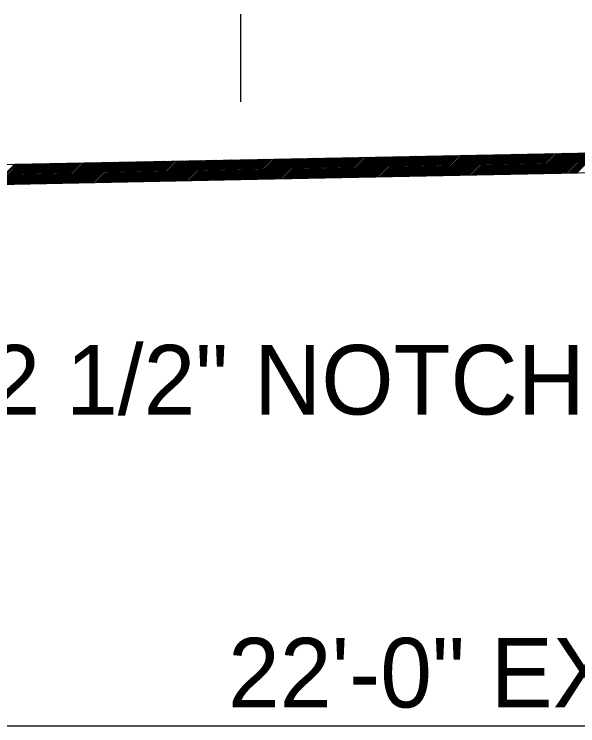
# Model space of a CAD drawing. Extents: x 2263886 to 2266026, y -3122850 to -3121850.
# Drawn here: x 2265591.65 to 2265596.51, y -3122413.5 to -3122407.37 of the extents above; entities that cross this region are included whole.
import ezdxf

# ---------------------------------------------------------------- set-up
doc = ezdxf.new("R2010")
doc.units = 0
doc.layers.add('R_Border Prem', color=7, linetype='Continuous')

msp = doc.modelspace()

# ---------------------------------------------------------------- linework, layer by layer
at = {"layer": 'R_Border Prem'}
for p, q in [((2265593.5991, -3122407.368), (2265593.5991, -3122408.123)), ((2265593.5991, -3122408.6231), (2265599.5991, -3122408.5031)), ((2265594.8123, -3122408.7688), (2265594.9858, -3122408.5953)), ((2265594.8267, -3122408.7685), (2265595.0002, -3122408.595)), ((2265594.8412, -3122408.7682), (2265595.0147, -3122408.5947)), ((2265594.8556, -3122408.768), (2265595.0291, -3122408.5945)), ((2265594.87, -3122408.7677), (2265595.0435, -3122408.5942)), ((2265594.8845, -3122408.7674), (2265595.058, -3122408.5939)), ((2265594.8989, -3122408.7671), (2265595.0724, -3122408.5936)), ((2265594.9133, -3122408.7668), (2265595.0868, -3122408.5933)), ((2265594.9278, -3122408.7665), (2265595.1013, -3122408.593)), ((2265594.9422, -3122408.7662), (2265595.1157, -3122408.5927)), ((2265594.9566, -3122408.7659), (2265595.1301, -3122408.5924)), ((2265594.971, -3122408.7656), (2265595.1446, -3122408.5921)), ((2265594.9855, -3122408.7654), (2265595.159, -3122408.5919)), ((2265594.9999, -3122408.7651), (2265595.1734, -3122408.5916)), ((2265595.0143, -3122408.7648), (2265595.1878, -3122408.5913)), ((2265595.0288, -3122408.7645), (2265595.2023, -3122408.591)), ((2265595.0432, -3122408.7642), (2265595.2167, -3122408.5907)), ((2265595.0576, -3122408.7639), (2265595.2311, -3122408.5904)), ((2265595.0721, -3122408.7636), (2265595.2456, -3122408.5901)), ((2265595.0865, -3122408.7633), (2265595.26, -3122408.5898)), ((2265595.1009, -3122408.7631), (2265595.2744, -3122408.5895)), ((2265595.1154, -3122408.7628), (2265595.2889, -3122408.5893)), ((2265595.1298, -3122408.7625), (2265595.3033, -3122408.589)), ((2265595.1442, -3122408.7622), (2265595.3177, -3122408.5887)), ((2265595.1586, -3122408.7619), (2265595.3322, -3122408.5884)), ((2265595.1731, -3122408.7616), (2265595.3466, -3122408.5881)), ((2265595.1875, -3122408.7613), (2265595.361, -3122408.5878)), ((2265595.2019, -3122408.761), (2265595.3754, -3122408.5875)), ((2265595.2164, -3122408.7607), (2265595.3899, -3122408.5872)), ((2265595.2308, -3122408.7605), (2265595.4043, -3122408.587)), ((2265595.2452, -3122408.7602), (2265595.4187, -3122408.5867)), ((2265595.2597, -3122408.7599), (2265595.4332, -3122408.5864)), ((2265595.2741, -3122408.7596), (2265595.4476, -3122408.5861)), ((2265595.2885, -3122408.7593), (2265595.462, -3122408.5858)), ((2265595.303, -3122408.759), (2265595.4765, -3122408.5855)), ((2265595.3174, -3122408.7587), (2265595.4909, -3122408.5852)), ((2265595.3318, -3122408.7584), (2265595.5053, -3122408.5849)), ((2265595.3462, -3122408.7581), (2265595.5197, -3122408.5846)), ((2265595.3607, -3122408.7579), (2265595.5342, -3122408.5844)), ((2265595.3751, -3122408.7576), (2265595.5486, -3122408.5841)), ((2265595.3895, -3122408.7573), (2265595.563, -3122408.5838)), ((2265595.404, -3122408.757), (2265595.5775, -3122408.5835)), ((2265595.4184, -3122408.7567), (2265595.5919, -3122408.5832)), ((2265595.4328, -3122408.7564), (2265595.6063, -3122408.5829)), ((2265595.4473, -3122408.7561), (2265595.6208, -3122408.5826)), ((2265595.4617, -3122408.7558), (2265595.6352, -3122408.5823)), ((2265595.4761, -3122408.7555), (2265595.6496, -3122408.582)), ((2265595.4906, -3122408.7553), (2265595.6641, -3122408.5818)), ((2265595.505, -3122408.755), (2265595.6785, -3122408.5815)), ((2265595.5194, -3122408.7547), (2265595.6929, -3122408.5812)), ((2265595.5338, -3122408.7544), (2265595.7073, -3122408.5809)), ((2265595.5483, -3122408.7541), (2265595.7218, -3122408.5806)), ((2265595.5627, -3122408.7538), (2265595.7362, -3122408.5803)), ((2265595.5771, -3122408.7535), (2265595.7506, -3122408.58)), ((2265595.5916, -3122408.7532), (2265595.7651, -3122408.5797)), ((2265595.606, -3122408.753), (2265595.7795, -3122408.5794)), ((2265595.6204, -3122408.7527), (2265595.7939, -3122408.5792)), ((2265595.6349, -3122408.7524), (2265595.8084, -3122408.5789)), ((2265595.6493, -3122408.7521), (2265595.8228, -3122408.5786)), ((2265595.6637, -3122408.7518), (2265595.8372, -3122408.5783)), ((2265595.6782, -3122408.7515), (2265595.8517, -3122408.578)), ((2265595.6926, -3122408.7512), (2265595.8661, -3122408.5777)), ((2265595.707, -3122408.7509), (2265595.8805, -3122408.5774)), ((2265595.7214, -3122408.7506), (2265595.8949, -3122408.5771)), ((2265595.7359, -3122408.7504), (2265595.9094, -3122408.5768)), ((2265595.7503, -3122408.7501), (2265595.9238, -3122408.5766)), ((2265595.7647, -3122408.7498), (2265595.9382, -3122408.5763)), ((2265595.7792, -3122408.7495), (2265595.9527, -3122408.576)), ((2265595.7936, -3122408.7492), (2265595.9671, -3122408.5757)), ((2265595.808, -3122408.7489), (2265595.9815, -3122408.5754)), ((2265595.8225, -3122408.7486), (2265595.996, -3122408.5751)), ((2265595.8369, -3122408.7483), (2265596.0104, -3122408.5748)), ((2265595.8513, -3122408.748), (2265596.0248, -3122408.5745)), ((2265595.8658, -3122408.7478), (2265596.0393, -3122408.5743)), ((2265595.8802, -3122408.7475), (2265596.0537, -3122408.574)), ((2265595.8946, -3122408.7472), (2265596.0681, -3122408.5737)), ((2265595.909, -3122408.7469), (2265596.0825, -3122408.5734)), ((2265595.9235, -3122408.7466), (2265596.097, -3122408.5731)), ((2265595.9379, -3122408.7463), (2265596.1114, -3122408.5728)), ((2265595.9523, -3122408.746), (2265596.1258, -3122408.5725)), ((2265595.9668, -3122408.7457), (2265596.1403, -3122408.5722)), ((2265595.9812, -3122408.7454), (2265596.1547, -3122408.5719)), ((2265595.9956, -3122408.7452), (2265596.1691, -3122408.5717)), ((2265596.0101, -3122408.7449), (2265596.1836, -3122408.5714)), ((2265596.0245, -3122408.7446), (2265596.198, -3122408.5711)), ((2265596.0389, -3122408.7443), (2265596.2124, -3122408.5708)), ((2265596.0534, -3122408.744), (2265596.2269, -3122408.5705)), ((2265596.0678, -3122408.7437), (2265596.2413, -3122408.5702)), ((2265596.0822, -3122408.7434), (2265596.2557, -3122408.5699)), ((2265596.0966, -3122408.7431), (2265596.2701, -3122408.5696)), ((2265596.1111, -3122408.7428), (2265596.2846, -3122408.5693)), ((2265596.1255, -3122408.7426), (2265596.299, -3122408.5691)), ((2265596.1399, -3122408.7423), (2265596.3134, -3122408.5688)), ((2265596.1544, -3122408.742), (2265596.3279, -3122408.5685)), ((2265596.1688, -3122408.7417), (2265596.3423, -3122408.5682)), ((2265596.1832, -3122408.7414), (2265596.3567, -3122408.5679)), ((2265596.1977, -3122408.7411), (2265596.3712, -3122408.5676)), ((2265596.2121, -3122408.7408), (2265596.3856, -3122408.5673)), ((2265596.2265, -3122408.7405), (2265596.4, -3122408.567)), ((2265596.241, -3122408.7403), (2265596.4145, -3122408.5667)), ((2265596.2554, -3122408.74), (2265596.4289, -3122408.5665)), ((2265596.2698, -3122408.7397), (2265596.4433, -3122408.5662)), ((2265596.2842, -3122408.7394), (2265596.4577, -3122408.5659)), ((2265596.2987, -3122408.7391), (2265596.4722, -3122408.5656)), ((2265596.3131, -3122408.7388), (2265596.4866, -3122408.5653)), ((2265596.3275, -3122408.7385), (2265596.501, -3122408.565)), ((2265596.342, -3122408.7382), (2265596.5155, -3122408.5647)), ((2265596.3564, -3122408.7379), (2265596.5299, -3122408.5644)), ((2265596.3708, -3122408.7377), (2265596.5443, -3122408.5641)), ((2265596.3853, -3122408.7374), (2265596.5588, -3122408.5639)), ((2265596.3997, -3122408.7371), (2265596.5732, -3122408.5636)), ((2265596.4141, -3122408.7368), (2265596.5876, -3122408.5633)), ((2265596.4286, -3122408.7365), (2265596.6021, -3122408.563)), ((2265596.443, -3122408.7362), (2265596.6165, -3122408.5627)), ((2265596.4574, -3122408.7359), (2265596.6309, -3122408.5624)), ((2265596.4718, -3122408.7356), (2265596.6453, -3122408.5621)), ((2265596.4863, -3122408.7353), (2265596.6598, -3122408.5618)), ((2265596.5007, -3122408.7351), (2265596.6742, -3122408.5616)), ((2265588.5991, -3122408.7231), (2265593.5991, -3122408.6231)), ((2265591.7386, -3122408.8303), (2265591.9121, -3122408.6568)), ((2265591.753, -3122408.83), (2265591.9265, -3122408.6565)), ((2265591.7674, -3122408.8297), (2265591.9409, -3122408.6562)), ((2265591.7819, -3122408.8294), (2265591.9554, -3122408.6559)), ((2265591.7963, -3122408.8291), (2265591.9698, -3122408.6556)), ((2265591.8107, -3122408.8289), (2265591.9842, -3122408.6554)), ((2265591.8251, -3122408.8286), (2265591.9986, -3122408.6551)), ((2265591.8396, -3122408.8283), (2265592.0131, -3122408.6548)), ((2265591.854, -3122408.828), (2265592.0275, -3122408.6545)), ((2265591.8684, -3122408.8277), (2265592.0419, -3122408.6542)), ((2265591.8829, -3122408.8274), (2265592.0564, -3122408.6539)), ((2265591.8973, -3122408.8271), (2265592.0708, -3122408.6536)), ((2265591.9117, -3122408.8268), (2265592.0852, -3122408.6533)), ((2265591.9262, -3122408.8265), (2265592.0997, -3122408.653)), ((2265591.9406, -3122408.8263), (2265592.1141, -3122408.6528)), ((2265591.955, -3122408.826), (2265592.1285, -3122408.6525)), ((2265591.9695, -3122408.8257), (2265592.143, -3122408.6522)), ((2265591.9839, -3122408.8254), (2265592.1574, -3122408.6519)), ((2265591.9983, -3122408.8251), (2265592.1718, -3122408.6516)), ((2265592.0127, -3122408.8248), (2265592.1862, -3122408.6513)), ((2265592.0272, -3122408.8245), (2265592.2007, -3122408.651)), ((2265592.0416, -3122408.8242), (2265592.2151, -3122408.6507)), ((2265592.056, -3122408.8239), (2265592.2295, -3122408.6504)), ((2265592.0705, -3122408.8237), (2265592.244, -3122408.6502)), ((2265592.0849, -3122408.8234), (2265592.2584, -3122408.6499)), ((2265592.0993, -3122408.8231), (2265592.2728, -3122408.6496)), ((2265592.1138, -3122408.8228), (2265592.2873, -3122408.6493)), ((2265592.1282, -3122408.8225), (2265592.3017, -3122408.649)), ((2265592.1426, -3122408.8222), (2265592.3161, -3122408.6487)), ((2265592.157, -3122408.8219), (2265592.3306, -3122408.6484)), ((2265592.1715, -3122408.8216), (2265592.345, -3122408.6481)), ((2265592.1859, -3122408.8214), (2265592.3594, -3122408.6478)), ((2265592.2003, -3122408.8211), (2265592.3738, -3122408.6476)), ((2265592.2148, -3122408.8208), (2265592.3883, -3122408.6473)), ((2265592.2292, -3122408.8205), (2265592.4027, -3122408.647)), ((2265592.2436, -3122408.8202), (2265592.4171, -3122408.6467)), ((2265592.2581, -3122408.8199), (2265592.4316, -3122408.6464)), ((2265592.2725, -3122408.8196), (2265592.446, -3122408.6461)), ((2265592.2869, -3122408.8193), (2265592.4604, -3122408.6458)), ((2265592.3014, -3122408.819), (2265592.4749, -3122408.6455)), ((2265592.3158, -3122408.8188), (2265592.4893, -3122408.6453)), ((2265592.3302, -3122408.8185), (2265592.5037, -3122408.645)), ((2265592.3446, -3122408.8182), (2265592.5182, -3122408.6447)), ((2265592.3591, -3122408.8179), (2265592.5326, -3122408.6444)), ((2265592.3735, -3122408.8176), (2265592.547, -3122408.6441)), ((2265592.3879, -3122408.8173), (2265592.5614, -3122408.6438)), ((2265592.4024, -3122408.817), (2265592.5759, -3122408.6435)), ((2265592.4168, -3122408.8167), (2265592.5903, -3122408.6432)), ((2265592.4312, -3122408.8164), (2265592.6047, -3122408.6429)), ((2265592.4457, -3122408.8162), (2265592.6192, -3122408.6427)), ((2265592.4601, -3122408.8159), (2265592.6336, -3122408.6424)), ((2265592.4745, -3122408.8156), (2265592.648, -3122408.6421)), ((2265592.489, -3122408.8153), (2265592.6625, -3122408.6418)), ((2265592.5034, -3122408.815), (2265592.6769, -3122408.6415)), ((2265592.5178, -3122408.8147), (2265592.6913, -3122408.6412)), ((2265592.5322, -3122408.8144), (2265592.7058, -3122408.6409)), ((2265592.5467, -3122408.8141), (2265592.7202, -3122408.6406)), ((2265592.5611, -3122408.8138), (2265592.7346, -3122408.6403)), ((2265592.5755, -3122408.8136), (2265592.749, -3122408.6401)), ((2265592.59, -3122408.8133), (2265592.7635, -3122408.6398)), ((2265592.6044, -3122408.813), (2265592.7779, -3122408.6395)), ((2265592.6188, -3122408.8127), (2265592.7923, -3122408.6392)), ((2265592.6333, -3122408.8124), (2265592.8068, -3122408.6389)), ((2265592.6477, -3122408.8121), (2265592.8212, -3122408.6386)), ((2265592.6621, -3122408.8118), (2265592.8356, -3122408.6383)), ((2265592.6766, -3122408.8115), (2265592.8501, -3122408.638)), ((2265592.691, -3122408.8113), (2265592.8645, -3122408.6377)), ((2265592.7054, -3122408.811), (2265592.8789, -3122408.6375)), ((2265592.7198, -3122408.8107), (2265592.8934, -3122408.6372)), ((2265592.7343, -3122408.8104), (2265592.9078, -3122408.6369)), ((2265592.7487, -3122408.8101), (2265592.9222, -3122408.6366)), ((2265592.7631, -3122408.8098), (2265592.9366, -3122408.6363)), ((2265592.7776, -3122408.8095), (2265592.9511, -3122408.636)), ((2265592.792, -3122408.8092), (2265592.9655, -3122408.6357)), ((2265592.8064, -3122408.8089), (2265592.9799, -3122408.6354)), ((2265592.8209, -3122408.8087), (2265592.9944, -3122408.6351)), ((2265592.8353, -3122408.8084), (2265593.0088, -3122408.6349)), ((2265592.8497, -3122408.8081), (2265593.0232, -3122408.6346)), ((2265592.8642, -3122408.8078), (2265593.0377, -3122408.6343)), ((2265592.8786, -3122408.8075), (2265593.0521, -3122408.634)), ((2265592.893, -3122408.8072), (2265593.0665, -3122408.6337)), ((2265592.9074, -3122408.8069), (2265593.081, -3122408.6334)), ((2265592.9219, -3122408.8066), (2265593.0954, -3122408.6331)), ((2265592.9363, -3122408.8063), (2265593.1098, -3122408.6328)), ((2265592.9507, -3122408.8061), (2265593.1242, -3122408.6326)), ((2265592.9652, -3122408.8058), (2265593.1387, -3122408.6323)), ((2265592.9796, -3122408.8055), (2265593.1531, -3122408.632)), ((2265592.994, -3122408.8052), (2265593.1675, -3122408.6317)), ((2265593.0085, -3122408.8049), (2265593.182, -3122408.6314)), ((2265593.0229, -3122408.8046), (2265593.1964, -3122408.6311)), ((2265593.0373, -3122408.8043), (2265593.2108, -3122408.6308)), ((2265593.0518, -3122408.804), (2265593.2253, -3122408.6305)), ((2265593.0662, -3122408.8037), (2265593.2397, -3122408.6302)), ((2265593.0806, -3122408.8035), (2265593.2541, -3122408.63)), ((2265593.095, -3122408.8032), (2265593.2686, -3122408.6297)), ((2265593.1095, -3122408.8029), (2265593.283, -3122408.6294)), ((2265593.1239, -3122408.8026), (2265593.2974, -3122408.6291)), ((2265593.1383, -3122408.8023), (2265593.3118, -3122408.6288)), ((2265593.1528, -3122408.802), (2265593.3263, -3122408.6285)), ((2265593.1672, -3122408.8017), (2265593.3407, -3122408.6282)), ((2265593.1816, -3122408.8014), (2265593.3551, -3122408.6279)), ((2265593.1961, -3122408.8011), (2265593.3696, -3122408.6276)), ((2265593.2105, -3122408.8009), (2265593.384, -3122408.6274)), ((2265593.2249, -3122408.8006), (2265593.3984, -3122408.6271)), ((2265593.2394, -3122408.8003), (2265593.4129, -3122408.6268)), ((2265593.2538, -3122408.8), (2265593.4273, -3122408.6265)), ((2265593.2682, -3122408.7997), (2265593.4417, -3122408.6262)), ((2265593.2826, -3122408.7994), (2265593.4562, -3122408.6259)), ((2265593.2971, -3122408.7991), (2265593.4706, -3122408.6256)), ((2265593.3115, -3122408.7988), (2265593.485, -3122408.6253)), ((2265593.3259, -3122408.7986), (2265593.4994, -3122408.625)), ((2265593.3404, -3122408.7983), (2265593.5139, -3122408.6248)), ((2265593.3548, -3122408.798), (2265593.5283, -3122408.6245)), ((2265593.3692, -3122408.7977), (2265593.5427, -3122408.6242)), ((2265593.3837, -3122408.7974), (2265593.5572, -3122408.6239)), ((2265593.3981, -3122408.7971), (2265593.5716, -3122408.6236)), ((2265593.4125, -3122408.7968), (2265593.586, -3122408.6233)), ((2265593.427, -3122408.7965), (2265593.6005, -3122408.623)), ((2265593.4414, -3122408.7962), (2265593.6149, -3122408.6227)), ((2265593.4558, -3122408.796), (2265593.6293, -3122408.6224)), ((2265593.4702, -3122408.7957), (2265593.6438, -3122408.6222)), ((2265593.4847, -3122408.7954), (2265593.6582, -3122408.6219)), ((2265593.4991, -3122408.7951), (2265593.6726, -3122408.6216)), ((2265593.5135, -3122408.7948), (2265593.687, -3122408.6213)), ((2265593.528, -3122408.7945), (2265593.7015, -3122408.621)), ((2265593.5424, -3122408.7942), (2265593.7159, -3122408.6207)), ((2265593.5568, -3122408.7939), (2265593.7303, -3122408.6204)), ((2265593.5713, -3122408.7936), (2265593.7448, -3122408.6201)), ((2265593.5857, -3122408.7934), (2265593.7592, -3122408.6199)), ((2265593.6001, -3122408.7931), (2265593.7736, -3122408.6196)), ((2265593.6146, -3122408.7928), (2265593.7881, -3122408.6193)), ((2265593.629, -3122408.7925), (2265593.8025, -3122408.619)), ((2265593.6434, -3122408.7922), (2265593.8169, -3122408.6187)), ((2265593.6578, -3122408.7919), (2265593.8314, -3122408.6184)), ((2265593.6723, -3122408.7916), (2265593.8458, -3122408.6181)), ((2265593.6867, -3122408.7913), (2265593.8602, -3122408.6178)), ((2265593.7011, -3122408.791), (2265593.8746, -3122408.6175)), ((2265593.7156, -3122408.7908), (2265593.8891, -3122408.6173)), ((2265593.73, -3122408.7905), (2265593.9035, -3122408.617)), ((2265593.7444, -3122408.7902), (2265593.9179, -3122408.6167)), ((2265593.7589, -3122408.7899), (2265593.9324, -3122408.6164)), ((2265593.7733, -3122408.7896), (2265593.9468, -3122408.6161)), ((2265593.7877, -3122408.7893), (2265593.9612, -3122408.6158)), ((2265593.8022, -3122408.789), (2265593.9757, -3122408.6155)), ((2265593.8166, -3122408.7887), (2265593.9901, -3122408.6152)), ((2265593.831, -3122408.7884), (2265594.0045, -3122408.6149)), ((2265593.8454, -3122408.7882), (2265594.019, -3122408.6147)), ((2265593.8599, -3122408.7879), (2265594.0334, -3122408.6144)), ((2265593.8743, -3122408.7876), (2265594.0478, -3122408.6141)), ((2265593.8887, -3122408.7873), (2265594.0622, -3122408.6138)), ((2265593.9032, -3122408.787), (2265594.0767, -3122408.6135)), ((2265593.9176, -3122408.7867), (2265594.0911, -3122408.6132)), ((2265593.932, -3122408.7864), (2265594.1055, -3122408.6129)), ((2265593.9465, -3122408.7861), (2265594.12, -3122408.6126)), ((2265593.9609, -3122408.7859), (2265594.1344, -3122408.6123)), ((2265593.9753, -3122408.7856), (2265594.1488, -3122408.6121)), ((2265593.9898, -3122408.7853), (2265594.1633, -3122408.6118)), ((2265594.0042, -3122408.785), (2265594.1777, -3122408.6115)), ((2265594.0186, -3122408.7847), (2265594.1921, -3122408.6112)), ((2265594.033, -3122408.7844), (2265594.2066, -3122408.6109)), ((2265594.0475, -3122408.7841), (2265594.221, -3122408.6106)), ((2265594.0619, -3122408.7838), (2265594.2354, -3122408.6103)), ((2265594.0763, -3122408.7835), (2265594.2498, -3122408.61)), ((2265594.0908, -3122408.7833), (2265594.2643, -3122408.6098)), ((2265594.1052, -3122408.783), (2265594.2787, -3122408.6095)), ((2265594.1196, -3122408.7827), (2265594.2931, -3122408.6092)), ((2265594.1341, -3122408.7824), (2265594.3076, -3122408.6089)), ((2265594.1485, -3122408.7821), (2265594.322, -3122408.6086)), ((2265594.1629, -3122408.7818), (2265594.3364, -3122408.6083)), ((2265594.1774, -3122408.7815), (2265594.3509, -3122408.608)), ((2265594.1918, -3122408.7812), (2265594.3653, -3122408.6077)), ((2265594.2062, -3122408.7809), (2265594.3797, -3122408.6074)), ((2265594.2206, -3122408.7807), (2265594.3942, -3122408.6072)), ((2265594.2351, -3122408.7804), (2265594.4086, -3122408.6069)), ((2265594.2495, -3122408.7801), (2265594.423, -3122408.6066)), ((2265594.2639, -3122408.7798), (2265594.4374, -3122408.6063)), ((2265594.2784, -3122408.7795), (2265594.4519, -3122408.606)), ((2265594.2928, -3122408.7792), (2265594.4663, -3122408.6057)), ((2265594.3072, -3122408.7789), (2265594.4807, -3122408.6054)), ((2265594.3217, -3122408.7786), (2265594.4952, -3122408.6051)), ((2265594.3361, -3122408.7783), (2265594.5096, -3122408.6048)), ((2265594.3505, -3122408.7781), (2265594.524, -3122408.6046)), ((2265594.365, -3122408.7778), (2265594.5385, -3122408.6043)), ((2265594.3794, -3122408.7775), (2265594.5529, -3122408.604)), ((2265594.3938, -3122408.7772), (2265594.5673, -3122408.6037)), ((2265594.4082, -3122408.7769), (2265594.5818, -3122408.6034)), ((2265594.4227, -3122408.7766), (2265594.5962, -3122408.6031)), ((2265594.4371, -3122408.7763), (2265594.6106, -3122408.6028)), ((2265594.4515, -3122408.776), (2265594.625, -3122408.6025)), ((2265594.466, -3122408.7758), (2265594.6395, -3122408.6022)), ((2265594.4804, -3122408.7755), (2265594.6539, -3122408.602)), ((2265594.4948, -3122408.7752), (2265594.6683, -3122408.6017)), ((2265594.5093, -3122408.7749), (2265594.6828, -3122408.6014)), ((2265594.5237, -3122408.7746), (2265594.6972, -3122408.6011)), ((2265594.5381, -3122408.7743), (2265594.7116, -3122408.6008)), ((2265594.5526, -3122408.774), (2265594.7261, -3122408.6005)), ((2265594.567, -3122408.7737), (2265594.7405, -3122408.6002)), ((2265594.5814, -3122408.7734), (2265594.7549, -3122408.5999)), ((2265594.5958, -3122408.7732), (2265594.7694, -3122408.5996)), ((2265594.6103, -3122408.7729), (2265594.7838, -3122408.5994)), ((2265594.6247, -3122408.7726), (2265594.7982, -3122408.5991)), ((2265594.6391, -3122408.7723), (2265594.8126, -3122408.5988)), ((2265594.6536, -3122408.772), (2265594.8271, -3122408.5985)), ((2265594.668, -3122408.7717), (2265594.8415, -3122408.5982)), ((2265594.6824, -3122408.7714), (2265594.8559, -3122408.5979)), ((2265594.6969, -3122408.7711), (2265594.8704, -3122408.5976)), ((2265594.7113, -3122408.7708), (2265594.8848, -3122408.5973)), ((2265594.7257, -3122408.7706), (2265594.8992, -3122408.5971)), ((2265594.7402, -3122408.7703), (2265594.9137, -3122408.5968)), ((2265594.7546, -3122408.77), (2265594.9281, -3122408.5965)), ((2265594.769, -3122408.7697), (2265594.9425, -3122408.5962)), ((2265594.7834, -3122408.7694), (2265594.957, -3122408.5959)), ((2265594.7979, -3122408.7691), (2265594.9714, -3122408.5956)), ((2265591.4788, -3122408.8355), (2265591.6523, -3122408.662)), ((2265591.4932, -3122408.8352), (2265591.6667, -3122408.6617)), ((2265591.5077, -3122408.8349), (2265591.6812, -3122408.6614)), ((2265591.5221, -3122408.8346), (2265591.6956, -3122408.6611)), ((2265591.5365, -3122408.8343), (2265591.71, -3122408.6608)), ((2265591.551, -3122408.8341), (2265591.7245, -3122408.6605)), ((2265591.5654, -3122408.8338), (2265591.7389, -3122408.6603)), ((2265591.5798, -3122408.8335), (2265591.7533, -3122408.66)), ((2265591.5943, -3122408.8332), (2265591.7678, -3122408.6597)), ((2265591.6087, -3122408.8329), (2265591.7822, -3122408.6594)), ((2265591.6231, -3122408.8326), (2265591.7966, -3122408.6591)), ((2265591.6375, -3122408.8323), (2265591.811, -3122408.6588)), ((2265591.652, -3122408.832), (2265591.8255, -3122408.6585)), ((2265591.6664, -3122408.8317), (2265591.8399, -3122408.6582)), ((2265591.6808, -3122408.8315), (2265591.8543, -3122408.6579)), ((2265591.6953, -3122408.8312), (2265591.8688, -3122408.6577)), ((2265591.7097, -3122408.8309), (2265591.8832, -3122408.6574)), ((2265591.7241, -3122408.8306), (2265591.8976, -3122408.6571)), ((2265593.6025, -3122408.793), (2265599.5991, -3122408.6731)), ((2265588.6025, -3122408.893), (2265593.6025, -3122408.793)), ((2265588.6025, -3122413.5031), (2265610.5957, -3122413.5031))]:
    msp.add_line(p, q, dxfattribs=at)

# ---------------------------------------------------------------- texts
msp.add_text('12 1/2" NOTCH', height=0.6, dxfattribs=at).set_placement((2265590.9793, -3122410.8194))
msp.add_text('22\'-0" EXISTING PAVEMENT', height=0.6, rotation=360, dxfattribs=at).set_placement((2265593.4928, -3122413.3455))

doc.saveas('drawing.dxf')
